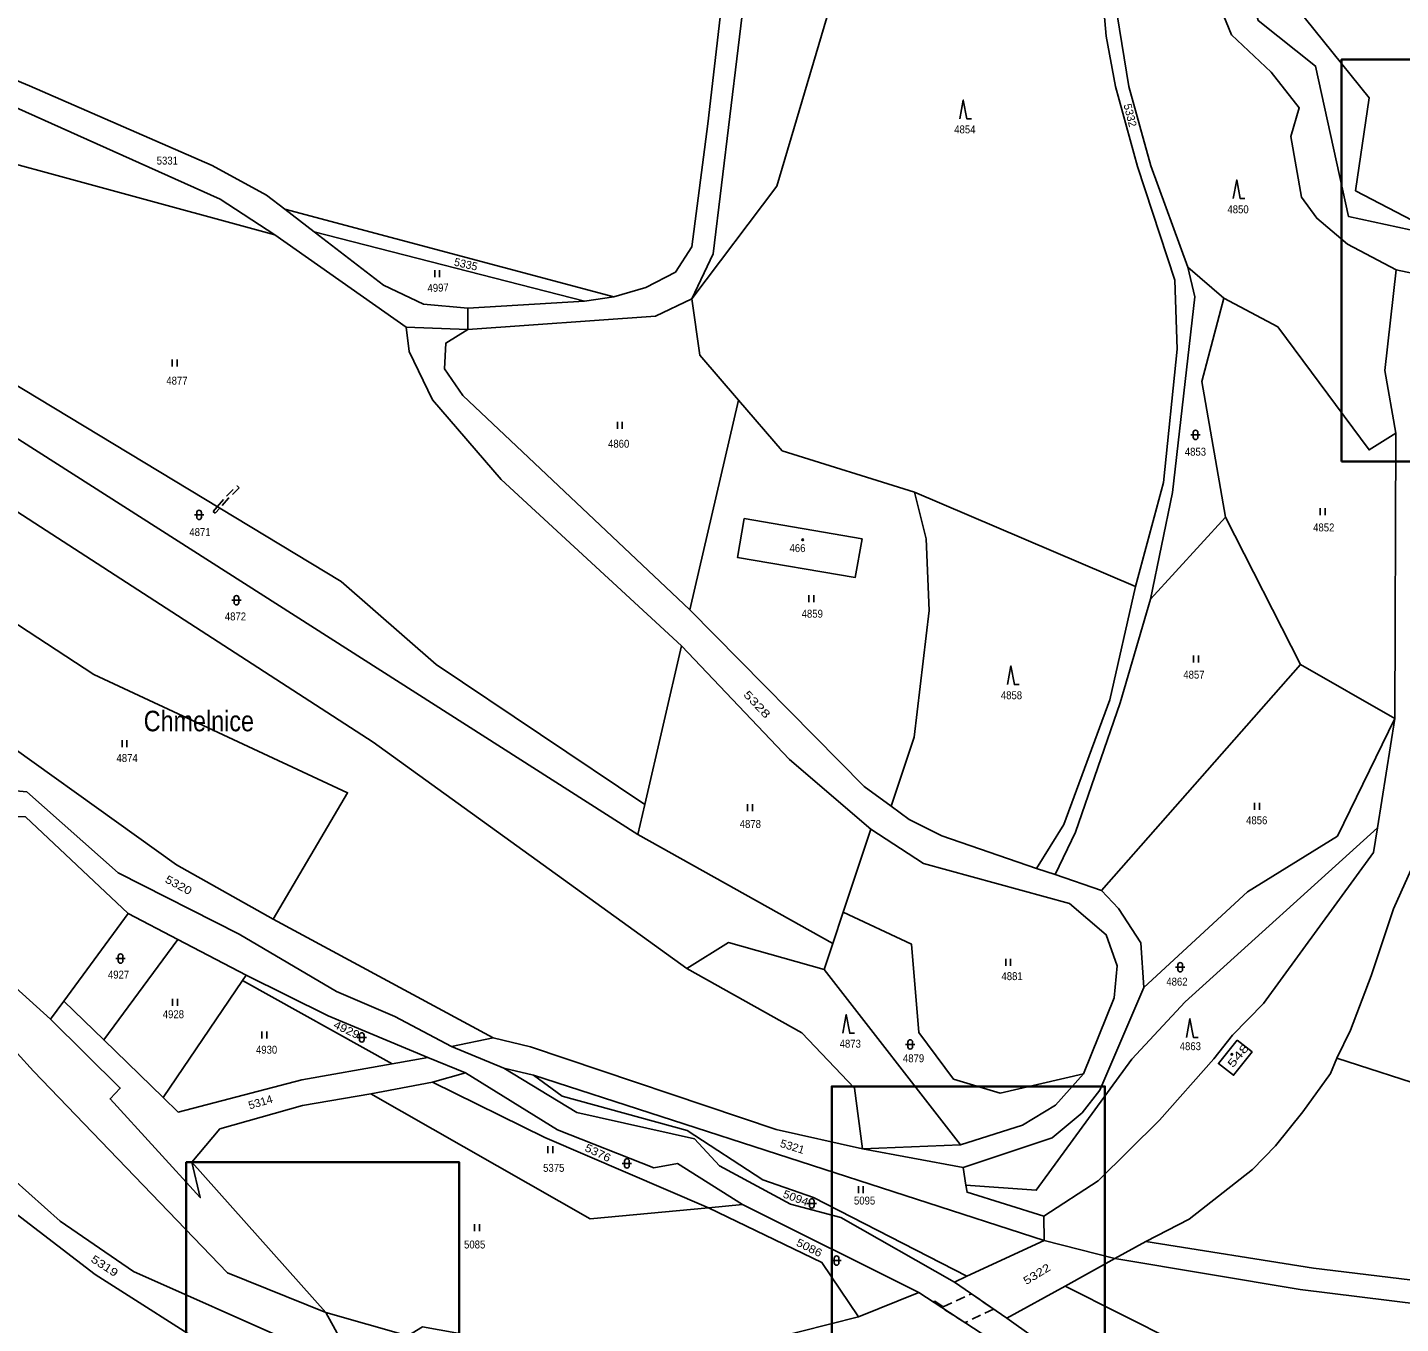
# Model space of a CAD drawing. Extents: x -665688 to -664583, y -1006118 to -1004927.
# Drawn here: x -665191.6 to -664897.5, y -1005454.1 to -1005176.4 of the extents above; entities that cross this region are included whole.
import ezdxf
from ezdxf.enums import TextEntityAlignment as Align

# ---------------------------------------------------------------- set-up
doc = ezdxf.new("R2010")
doc.units = 0
doc.header["$LTSCALE"] = 0.68
doc.linetypes.add('MEDIUM_DASHED', pattern=[4.5, 3, -1.5])
for name, color, linetype, lineweight in [('1', 7, 'Continuous', 25), ('25', 7, 'Continuous', 25), ('27', 7, 'MEDIUM_DASHED', 25), ('55', 7, 'Continuous', 35)]:
    doc.layers.add(name, color=color, linetype=linetype, lineweight=lineweight)
for name, color, linetype in [('15', 7, 'Continuous'), ('18', 7, 'Continuous'), ('19', 7, 'Continuous')]:
    doc.layers.add(name, color=color, linetype=linetype)

msp = doc.modelspace()

# ---------------------------------------------------------------- linework, layer by layer
at = {"layer": '1'}
for p, q in [((-665097.3, -1005241.05), (-665097.26, -1005236.54)), ((-665072.31, -1005234.98), (-665097.26, -1005236.54)), ((-665097.3, -1005241.05), (-665110.5, -1005240.56)), ((-664898.65, -1005324.46), (-664898.46, -1005263.33)), ((-664918.88, -1005312.89), (-664898.65, -1005324.46)), ((-664898.65, -1005324.46), (-664902.37, -1005347.86)), ((-664971.46, -1005357.88), (-664975.48, -1005356.59)), ((-665170.08, -1005366.25), (-665159.4, -1005371.83)), ((-665159.4, -1005371.83), (-665144.78, -1005379.46)), ((-665019.11, -1005372.67), (-665020.96, -1005378.24)), ((-665091.86, -1005392.84), (-665100.81, -1005394.75)), ((-665089.55, -1005399.37), (-665100.81, -1005394.75)), ((-665105.89, -1005397.05), (-665097.79, -1005400.37)), ((-665089.55, -1005399.37), (-665083.2, -1005400.84)), ((-665118.08, -1005404.88), (-665104.85, -1005402.34)), ((-664991.18, -1005420.63), (-665012.73, -1005416.63)), ((-665038.41, -1005428.56), (-665000.67, -1005447.45)), ((-664969.3, -1005446.1), (-664958.68, -1005440.16)), ((-664981.8, -1005452.97), (-664993.04, -1005445.2)), ((-664981.8, -1005452.97), (-664969.3, -1005446.1)), ((-665000.67, -1005447.45), (-665013.61, -1005452.67)), ((-665000.67, -1005447.45), (-664985.67, -1005457.24))]:
    msp.add_line(p, q, dxfattribs=at)
for points in [[(-664895.39, -1005219.73), (-664908.63, -1005216.84), (-664915.67, -1005184.63), (-664927.97, -1005174.84), (-664931.29, -1005161.96), (-664923.13, -1005157.75), (-664909.4, -1005145.58), (-664903.94, -1005133.92), (-664903.15, -1005127.85), (-664912.19, -1005084.06), (-664891.68, -1005067.49), (-664871.95, -1005045.77), (-664858.98, -1005033.99), (-664851.57, -1005033.48)], [(-664894.9, -1005217.74), (-664907.14, -1005211.36), (-664904.2, -1005191.46), (-664923.77, -1005167.11), (-664902.42, -1005142.29), (-664899.45, -1005128.56), (-664907.27, -1005091.69), (-664905.43, -1005083.63), (-664892.51, -1005077.23), (-664870.34, -1005046.85), (-664858.99, -1005037.17), (-664850.64, -1005036.62)], [(-665136.5, -1005215.33), (-665140.44, -1005212.3), (-665152.07, -1005205.93), (-665191.17, -1005188.9), (-665218.73, -1005177.39), (-665216.13, -1005170.52), (-665206.49, -1005145), (-665182.51, -1005081.53)], [(-665049.31, -1005234.5), (-665044.7, -1005224.87), (-665033.98, -1005136.54), (-665026.72, -1005106.52)], [(-665001.26, -1005109.58), (-665031.11, -1005210.37), (-665049.31, -1005234.5)], [(-664968.96, -1005115.26), (-664961.42, -1005140.2), (-664960.58, -1005145.04), (-664961.76, -1005164.25), (-664960.54, -1005178.21), (-664958.55, -1005188.98), (-664953.84, -1005206.17), (-664945.82, -1005230.5), (-664945.31, -1005245.28), (-664948.24, -1005273.87), (-664954.26, -1005296.16), (-665001.62, -1005275.92)], [(-665035.77, -1005123.25), (-665038.71, -1005135.19), (-665045.89, -1005196.99), (-665049.31, -1005223.37), (-665052.82, -1005228.77), (-665059.13, -1005232.1), (-665065.99, -1005234.1)], [(-664943, -1005227.75), (-664950.93, -1005206.04), (-664955.68, -1005188.99), (-664958.69, -1005170.55), (-664939.22, -1005164.33)], [(-664939.22, -1005164.33), (-664933.7, -1005177.92), (-664925.15, -1005185.97), (-664919.15, -1005193.6), (-664920.98, -1005199.71), (-664918.67, -1005212.71), (-664915.42, -1005217.25), (-664908.82, -1005222.82), (-664898.36, -1005228.3)], [(-665240.86, -1005177.51), (-665205.31, -1005188.54), (-665150.34, -1005213.14), (-665138.6, -1005220.79)], [(-665059.37, -1005342.9), (-665104.09, -1005312.9), (-665124.43, -1005295.1), (-665225.03, -1005234.3), (-665246.42, -1005229.05), (-665242.48, -1005192.49)], [(-665242.48, -1005192.49), (-665138.6, -1005220.79), (-665110.5, -1005240.56)], [(-665399.75, -1005208.35), (-665376.11, -1005222.26), (-665358.6, -1005232.91), (-665344.4, -1005243.08), (-665327.83, -1005258.99), (-665299.41, -1005297.42), (-665287.03, -1005311.31), (-665268.55, -1005328.24), (-665251.87, -1005341.72), (-665211.4, -1005376.84), (-665190.33, -1005399.99), (-665148.79, -1005443.19), (-665127.68, -1005451.74), (-665121.7, -1005462.65), (-665134.58, -1005458.21)], [(-665050.35, -1005378.04), (-665117.56, -1005329.51), (-665248.06, -1005245.09), (-665261.76, -1005239.56), (-665293.79, -1005218.72), (-665304.45, -1005209.39)], [(-665097.26, -1005236.54), (-665106.75, -1005235.64), (-665115.37, -1005231.58), (-665130.24, -1005220.14)], [(-664951.06, -1005298.9), (-664946.29, -1005275.99), (-664941.51, -1005234.09), (-664943, -1005227.75)], [(-664898.46, -1005263.33), (-664904.2, -1005266.89), (-664923.76, -1005240.51), (-664935.35, -1005234.38), (-664943, -1005227.75)], [(-664898.36, -1005228.3), (-664900.84, -1005249.89), (-664898.46, -1005263.33)], [(-664898.36, -1005228.3), (-664873.52, -1005233.6), (-664874.22, -1005299.23)], [(-665097.3, -1005241.05), (-665057.09, -1005238.2), (-665049.31, -1005234.5)], [(-665049.31, -1005234.5), (-665047.61, -1005246.59), (-665039.32, -1005256.22), (-665049.72, -1005301.17)], [(-664934.98, -1005281.28), (-664940.03, -1005252.24), (-664935.35, -1005234.38)], [(-665247.28, -1005237.07), (-665218.64, -1005248.65), (-665060.85, -1005349.31)], [(-665110.5, -1005240.56), (-665109.84, -1005245.77), (-665104.86, -1005256.16), (-665090.12, -1005273.19), (-665051.5, -1005308.87), (-665059.37, -1005342.9)], [(-665049.72, -1005301.17), (-665098.35, -1005255.21), (-665102.3, -1005249.51), (-665102, -1005243.98), (-665097.3, -1005241.05)], [(-665001.62, -1005275.92), (-665029.94, -1005267.11), (-665039.32, -1005256.22)], [(-665001.62, -1005275.92), (-664999.1, -1005285.91), (-664998.44, -1005301.31), (-665001.69, -1005328.42), (-665006.62, -1005343.23)], [(-665186.72, -1005388.88), (-665231.73, -1005348.14), (-665247.24, -1005335.03), (-665262.9, -1005322.2), (-665284.22, -1005302.33), (-665295.64, -1005288.54), (-665288.78, -1005281.42)], [(-665288.78, -1005281.42), (-665278.12, -1005293.76), (-665254.75, -1005298.72), (-665246.23, -1005320.3), (-665241.95, -1005328.41), (-665229.65, -1005333.27), (-665213.43, -1005330.83), (-665203.9, -1005345.02), (-665192.06, -1005345.49), (-665170.08, -1005366.25)], [(-664934.98, -1005281.28), (-664918.88, -1005312.89), (-664961.49, -1005361.3), (-664971.46, -1005357.88)], [(-664971.46, -1005357.88), (-664967.09, -1005348.78), (-664957.49, -1005321.11), (-664951.06, -1005298.9), (-664934.98, -1005281.28)], [(-664975.48, -1005356.59), (-664969.6, -1005347.14), (-664959.71, -1005320.47), (-664954.26, -1005296.16)], [(-665139.02, -1005367.43), (-665159.72, -1005355.83), (-665207.38, -1005321.62), (-665218.42, -1005320.08), (-665199.64, -1005300.53)], [(-665199.64, -1005300.53), (-665177.42, -1005315.04), (-665123.06, -1005340.35), (-665139.02, -1005367.43)], [(-665006.62, -1005343.23), (-665012.38, -1005338.99), (-665049.72, -1005301.17)], [(-665051.5, -1005308.87), (-665028.39, -1005333.21), (-665010.97, -1005348.18), (-665016.87, -1005365.92), (-665019.11, -1005372.67), (-665060.85, -1005349.31), (-665059.37, -1005342.9)], [(-664911.11, -1005397.23), (-664908.16, -1005391.22), (-664903.76, -1005379.6), (-664898.99, -1005365.23), (-664880.44, -1005324.02), (-664875.64, -1005308.45)], [(-665100.81, -1005394.75), (-665112.89, -1005388.29), (-665125.42, -1005382.92), (-665146.27, -1005370.65), (-665172.18, -1005357.52), (-665191.77, -1005340.12), (-665198.15, -1005339.57), (-665203.62, -1005332.13), (-665212.87, -1005325.35), (-665222.91, -1005324.76)], [(-664898.65, -1005324.46), (-664910.98, -1005349.63), (-664930.26, -1005361.6), (-664952.48, -1005382.07)], [(-664975.48, -1005356.59), (-664995.7, -1005349.58), (-665002.76, -1005346.07), (-665006.62, -1005343.23)], [(-665010.97, -1005348.18), (-664999.64, -1005355.54), (-664968.37, -1005364.11), (-664960.56, -1005370.78), (-664958.18, -1005377.42), (-664958.78, -1005384.32), (-664965.36, -1005400.61)], [(-664902.37, -1005347.86), (-664943.61, -1005385.12), (-664955.01, -1005397.41), (-664975.49, -1005425.51), (-664990.58, -1005424.46), (-664991.18, -1005420.63)], [(-664902.37, -1005347.86), (-664903.22, -1005353.17), (-664926.83, -1005385.53), (-664933.44, -1005392.32), (-664937.47, -1005397.34), (-664949.13, -1005410.53), (-664962.23, -1005423.51), (-664973.85, -1005431.1)], [(-664952.48, -1005382.07), (-664953.08, -1005372.54), (-664957.87, -1005365.15), (-664961.49, -1005361.3)], [(-665170.08, -1005366.25), (-665183.86, -1005384.99), (-665186.72, -1005388.88)], [(-665016.87, -1005365.92), (-665002.22, -1005372.83), (-665000.64, -1005391.69), (-664993.21, -1005401.74), (-664983.24, -1005404.71), (-664965.36, -1005400.61)], [(-665012.73, -1005416.63), (-665031.21, -1005412.54), (-665083.85, -1005394.79), (-665091.86, -1005392.84), (-665139.02, -1005367.43)], [(-665159.4, -1005371.83), (-665175.28, -1005393.3), (-665183.86, -1005384.99)], [(-665020.96, -1005378.24), (-665041.41, -1005372.47), (-665050.35, -1005378.04)], [(-664847.73, -1005373.11), (-664853.38, -1005372.05), (-664890.31, -1005403.96), (-664911.11, -1005397.23)], [(-665050.35, -1005378.04), (-665025.75, -1005391.78), (-665014.41, -1005403.65), (-665012.73, -1005416.63)], [(-665020.96, -1005378.24), (-664991.72, -1005415.78), (-665012.73, -1005416.63)], [(-665145.53, -1005380.57), (-665162.55, -1005405.66), (-665175.28, -1005393.3)], [(-665105.89, -1005397.05), (-665113.52, -1005398.42), (-665145.53, -1005380.57), (-665144.78, -1005379.46)], [(-665144.78, -1005379.46), (-665127.19, -1005388.15), (-665105.89, -1005397.05)], [(-664991.18, -1005420.63), (-664972.09, -1005414.33), (-664965.7, -1005408.91), (-664961.91, -1005404.06), (-664952.48, -1005382.07)], [(-665156.4, -1005419.5), (-665154.61, -1005427.1), (-665173.94, -1005405.95), (-665171.75, -1005403.64), (-665186.72, -1005388.88)], [(-665113.52, -1005398.42), (-665132.82, -1005401.87), (-665159.35, -1005408.77), (-665162.55, -1005405.66)], [(-664993.04, -1005445.2), (-665017.35, -1005431.35), (-665028.16, -1005428.51), (-665043.37, -1005420.31), (-665048.74, -1005414.54), (-665073.92, -1005408.87), (-665089.55, -1005399.37)], [(-664911.11, -1005397.23), (-664912.46, -1005400.49), (-664918.41, -1005408.69), (-664924.27, -1005416.02), (-664929.2, -1005421.1), (-664942.75, -1005431.69), (-664952, -1005436.49), (-664958.68, -1005440.16), (-664973.84, -1005436.33), (-664973.85, -1005431.1)], [(-665045.75, -1005429.26), (-665080.8, -1005414.25), (-665104.85, -1005402.34), (-665097.79, -1005400.37)], [(-665097.79, -1005400.37), (-665078.05, -1005412.57), (-665057.45, -1005420.7), (-665052.37, -1005419.81), (-665038.41, -1005428.56)], [(-665083.2, -1005400.84), (-664973.84, -1005436.33), (-664990.35, -1005443.96)], [(-665083.2, -1005400.84), (-665077.11, -1005405.36), (-665050.32, -1005412.75), (-665034.07, -1005423.33), (-665023.2, -1005427.08), (-664990.35, -1005443.96), (-664993.04, -1005445.2)], [(-664965.36, -1005400.61), (-664971.4, -1005407.3), (-664978.47, -1005411.61), (-664991.72, -1005415.78)], [(-665156.4, -1005419.5), (-665150.41, -1005412.37), (-665132.72, -1005407.37), (-665118.08, -1005404.88)], [(-665118.08, -1005404.88), (-665071.08, -1005431.67), (-665045.75, -1005429.26)], [(-665136.29, -1005477.24), (-665150.22, -1005460.69), (-665177.15, -1005443.61), (-665221.19, -1005409.78), (-665210.58, -1005407.96)], [(-665210.58, -1005407.96), (-665198.15, -1005420.12), (-665184.6, -1005432.15), (-665168.91, -1005442.94), (-665134.58, -1005458.21), (-665131.02, -1005461.53)], [(-665013.61, -1005452.67), (-665032.2, -1005457.35), (-665049.69, -1005459.74), (-665076.88, -1005460.21), (-665107.01, -1005454.78), (-665110.17, -1005456.74), (-665127.68, -1005451.74), (-665156.4, -1005419.5)], [(-664973.85, -1005431.1), (-664990.34, -1005425.94), (-664990.58, -1005424.46)], [(-665013.61, -1005452.67), (-665021.41, -1005441.03), (-665045.75, -1005429.26), (-665038.41, -1005428.56)], [(-664812.89, -1005451.45), (-664818.34, -1005452.22), (-664821.75, -1005452.39), (-664832, -1005452.23), (-664844.79, -1005450.86), (-664916.08, -1005442.22), (-664952, -1005436.49)], [(-664958.68, -1005440.16), (-664918.99, -1005446.77), (-664835.18, -1005457.14), (-664824.19, -1005457.34), (-664809.08, -1005455.92), (-664802.4, -1005456.42), (-664792.15, -1005466.99), (-664796.78, -1005468.06), (-664803.23, -1005465.97)], [(-664969.3, -1005446.1), (-664945.43, -1005458.11), (-664870.22, -1005475.95), (-664843.38, -1005478.52), (-664808.84, -1005489.57), (-664807.3, -1005497.72)], [(-664807.3, -1005497.72), (-664823.52, -1005498.49), (-664831.43, -1005490.72), (-664845.63, -1005484.35), (-664861.39, -1005491.91), (-664864, -1005488.5), (-664869.71, -1005485.89), (-664886.34, -1005486.35), (-664888.54, -1005481.42), (-664895.39, -1005478.51), (-664911.15, -1005478.85), (-664917.14, -1005475.22), (-664920.29, -1005468.16), (-664939.44, -1005469.7), (-664948.5, -1005477.86), (-664952.19, -1005476.3), (-664954.45, -1005466.18), (-664962.99, -1005461.77), (-664976.12, -1005457.02), (-664981.8, -1005452.97)]]:
    msp.add_lwpolyline(points, dxfattribs=at)
for points in [[(-665136.5, -1005215.33), (-665065.99, -1005234.1), (-665072.31, -1005234.98), (-665130.24, -1005220.14)], [(-665038.07, -1005281.58), (-665039.49, -1005289.96), (-665014.27, -1005294.21), (-665012.82, -1005285.97)], [(-664932.47, -1005393.36), (-664936.49, -1005398.39), (-664933.24, -1005400.88), (-664929.25, -1005395.88)]]:
    msp.add_lwpolyline(points, close=True, dxfattribs=at)
at = {"layer": '25'}
for p, q in [((-665104.357, -1005229.855), (-665104.357, -1005228.355)), ((-665103.323, -1005229.855), (-665103.323, -1005228.355)), ((-665160.627, -1005249.025), (-665160.627, -1005247.525)), ((-665159.593, -1005249.025), (-665159.593, -1005247.525)), ((-665065.237, -1005262.335), (-665065.237, -1005260.835)), ((-665064.203, -1005262.335), (-665064.203, -1005260.835)), ((-664942.37, -1005263.66), (-664940.37, -1005263.66)), ((-664941.87, -1005264.16), (-664941.87, -1005263.16)), ((-664940.87, -1005263.16), (-664940.87, -1005264.16)), ((-665155.87, -1005280.82), (-665153.87, -1005280.82)), ((-665155.37, -1005281.32), (-665155.37, -1005280.32)), ((-665154.37, -1005280.32), (-665154.37, -1005281.32)), ((-664914.667, -1005280.895), (-664914.667, -1005279.395)), ((-664913.633, -1005280.895), (-664913.633, -1005279.395)), ((-665147.86, -1005299.1), (-665145.86, -1005299.1)), ((-665147.36, -1005299.6), (-665147.36, -1005298.6)), ((-665146.36, -1005298.6), (-665146.36, -1005299.6)), ((-665024.207, -1005299.535), (-665024.207, -1005298.035)), ((-665023.173, -1005299.535), (-665023.173, -1005298.035)), ((-664941.797, -1005312.425), (-664941.797, -1005310.925)), ((-664940.763, -1005312.425), (-664940.763, -1005310.925)), ((-665171.367, -1005330.615), (-665171.367, -1005329.115)), ((-665170.333, -1005330.615), (-665170.333, -1005329.115)), ((-665037.357, -1005344.265), (-665037.357, -1005342.765)), ((-665036.323, -1005344.265), (-665036.323, -1005342.765)), ((-664928.727, -1005344.015), (-664928.727, -1005342.515)), ((-664927.693, -1005344.015), (-664927.693, -1005342.515)), ((-665172.69, -1005375.88), (-665170.69, -1005375.88)), ((-665172.19, -1005376.38), (-665172.19, -1005375.38)), ((-665171.19, -1005375.38), (-665171.19, -1005376.38)), ((-664982.047, -1005377.465), (-664982.047, -1005375.965)), ((-664981.013, -1005377.465), (-664981.013, -1005375.965)), ((-664945.64, -1005377.74), (-664943.64, -1005377.74)), ((-664945.14, -1005378.24), (-664945.14, -1005377.24)), ((-664944.14, -1005377.24), (-664944.14, -1005378.24)), ((-665160.547, -1005386.045), (-665160.547, -1005384.545)), ((-665159.513, -1005386.045), (-665159.513, -1005384.545)), ((-665141.387, -1005393.005), (-665141.387, -1005391.505)), ((-665140.353, -1005393.005), (-665140.353, -1005391.505)), ((-665121.01, -1005392.77), (-665119.01, -1005392.77)), ((-665120.51, -1005393.27), (-665120.51, -1005392.27)), ((-665119.51, -1005392.27), (-665119.51, -1005393.27)), ((-665003.51, -1005394.29), (-665001.51, -1005394.29)), ((-665003.01, -1005394.79), (-665003.01, -1005393.79)), ((-665002.01, -1005393.79), (-665002.01, -1005394.79)), ((-665080.117, -1005417.555), (-665080.117, -1005416.055)), ((-665079.083, -1005417.555), (-665079.083, -1005416.055)), ((-665064.2, -1005419.79), (-665062.2, -1005419.79)), ((-665063.7, -1005420.29), (-665063.7, -1005419.29)), ((-665062.7, -1005419.29), (-665062.7, -1005420.29)), ((-665013.617, -1005426.155), (-665013.617, -1005424.655)), ((-665012.583, -1005426.155), (-665012.583, -1005424.655)), ((-665024.59, -1005428.36), (-665022.59, -1005428.36)), ((-665024.09, -1005428.86), (-665024.09, -1005427.86)), ((-665023.09, -1005427.86), (-665023.09, -1005428.86)), ((-665095.847, -1005434.315), (-665095.847, -1005432.815)), ((-665094.813, -1005434.315), (-665094.813, -1005432.815)), ((-665019.29, -1005440.6), (-665017.29, -1005440.6)), ((-665018.79, -1005441.1), (-665018.79, -1005440.1)), ((-665017.79, -1005440.1), (-665017.79, -1005441.1))]:
    msp.add_line(p, q, dxfattribs=at)
for points in [[(-664991.91, -1005195.94), (-664991.16, -1005191.94), (-664990.41, -1005195.94), (-664989.41, -1005195.94)], [(-664933.3, -1005213.02), (-664932.55, -1005209.02), (-664931.8, -1005213.02), (-664930.8, -1005213.02)], [(-664981.68, -1005317.16), (-664980.93, -1005313.16), (-664980.18, -1005317.16), (-664979.18, -1005317.16)], [(-665016.95, -1005391.9), (-665016.2, -1005387.9), (-665015.45, -1005391.9), (-665014.45, -1005391.9)], [(-664943.32, -1005392.79), (-664942.57, -1005388.79), (-664941.82, -1005392.79), (-664940.82, -1005392.79)]]:
    msp.add_lwpolyline(points, dxfattribs=at)
for centre in [(-665025.56, -1005286.14), (-664933.6, -1005396.42)]:
    msp.add_circle(centre, 0.175, dxfattribs=at)
for centre, start, end in [((-664941.37, -1005263.16), 0.101, 180.00143), ((-664941.37, -1005264.16), 180.10243, 0.00286), ((-665154.87, -1005280.32), 0.101, 180.00143), ((-665154.87, -1005281.32), 180.10243, 0.00286), ((-665146.86, -1005298.6), 0.101, 180.00143), ((-665146.86, -1005299.6), 180.10243, 0.00286), ((-665171.69, -1005375.38), 0.101, 180.00143), ((-665171.69, -1005376.38), 180.10243, 0.00286), ((-664944.64, -1005377.24), 0.101, 180.00143), ((-664944.64, -1005378.24), 180.10243, 0.00286), ((-665120.01, -1005392.27), 0.101, 180.00143), ((-665120.01, -1005393.27), 180.10243, 0.00286), ((-665002.51, -1005393.79), 0.101, 180.00143), ((-665002.51, -1005394.79), 180.10243, 0.00286), ((-665063.2, -1005419.29), 0.101, 180.00143), ((-665063.2, -1005420.29), 180.10243, 0.00286), ((-665023.59, -1005427.86), 0.101, 180.00143), ((-665023.59, -1005428.86), 180.10243, 0.00286), ((-665018.29, -1005440.1), 0.101, 180.00143), ((-665018.29, -1005441.1), 180.10243, 0.00286)]:
    msp.add_arc(centre, 0.5, start, end, dxfattribs=at)
at = {"layer": '27'}
for points in [[(-665146.69, -1005274.57), (-665146.27, -1005274.99), (-665148.55, -1005277.25), (-665150.44, -1005279.38), (-665151.4, -1005280.47), (-665151.85, -1005280.08), (-665150.96, -1005279.07), (-665148.99, -1005276.83)], [(-664997.63, -1005449.44), (-664997.23, -1005449.28), (-664995.44, -1005450.48), (-664989.37, -1005447.74), (-664984.65, -1005451), (-664990.78, -1005453.9)]]:
    msp.add_lwpolyline(points, close=True, dxfattribs=at)
at = {"layer": '55'}
for points in [[(-664910.13, -1005269.36), (-664910.13, -1005183.26), (-664851.63, -1005183.26), (-664851.63, -1005269.36)], [(-665019.3, -1005489.36), (-665019.3, -1005403.26), (-664960.8, -1005403.26), (-664960.8, -1005489.36)], [(-665157.63, -1005505.61), (-665157.63, -1005419.51), (-665099.13, -1005419.51), (-665099.13, -1005505.61)]]:
    msp.add_lwpolyline(points, close=True, dxfattribs=at)

# ---------------------------------------------------------------- texts
at = {"layer": '15', "width": 0.85}
msp.add_text('Chmelnice', height=4.4, dxfattribs=at).set_placement((-665154.91, -1005327.18), align=Align.CENTER)
at = {"layer": '18'}
for s, rotation, p in [('5332', 284.302, (-664956.194, -1005195.3945)), ('5335', 347.203, (-665097.8878, -1005227.9241))]:
    msp.add_text(s, height=1.7, rotation=rotation, dxfattribs=at).set_placement(p, align=Align.CENTER)
at = {"layer": '18', "width": 0.9}
for s, p in [('4854', (-664990.7995, -1005199.06)), ('5331', (-665161.6695, -1005205.74)), ('4850', (-664932.2695, -1005216.18)), ('4877', (-665159.5995, -1005252.89)), ('4860', (-665064.9695, -1005266.41)), ('4853', (-664941.3995, -1005268.12)), ('4871', (-665154.6695, -1005285.34)), ('4852', (-664913.9095, -1005284.35)), ('4872', (-665147.0695, -1005303.42)), ('4859', (-665023.4895, -1005302.84)), ('4857', (-664941.7195, -1005315.89)), ('4858', (-664980.8095, -1005320.31)), ('4874', (-665170.2795, -1005333.76)), ('4878', (-665036.7595, -1005347.89)), ('4856', (-664928.2695, -1005347.1)), ('4927', (-665172.1195, -1005380.17)), ('4881', (-664980.6795, -1005380.5)), ('4862', (-664945.3595, -1005381.68)), ('4928', (-665160.3695, -1005388.66)), ('4873', (-665015.3495, -1005394.97)), ('4930', (-665140.3995, -1005396.26)), ('4879', (-665001.7895, -1005398.1)), ('4863', (-664942.4895, -1005395.51)), ('5375', (-665078.8795, -1005421.58)), ('5095', (-665012.2795, -1005428.59)), ('5085', (-665095.8195, -1005438))]:
    msp.add_text(s, height=1.7, dxfattribs=at).set_placement(p, align=Align.CENTER)
at = {"layer": '18'}
for s, rotation, width, p in [('4997', 1.7, 0.9, (-665103.6317, -1005232.9815)), ('5328', 313.402, 1.4, (-665035.9492, -1005322.003)), ('5320', 331.703, 1.2, (-665159.6544, -1005360.8756)), ('4929', 334.703, 1.15, (-665123.6157, -1005391.8805)), ('5314', 16.6, 1.05, (-665141.4698, -1005407.466)), ('5376', 334.303, 1.15, (-665069.7831, -1005418.2691)), ('5321', 342.803, 1.05, (-665027.9908, -1005416.9805)), ('5094', 339.603, 1.1, (-665027.3242, -1005427.9694)), ('5086', 333.403, 1.15, (-665024.5066, -1005438.5971)), ('5319', 327.003, 1.25, (-665175.5624, -1005442.4438)), ('5322', 31.5, 1.25, (-664974.9351, -1005444.2067))]:
    msp.add_text(s, height=1.7, rotation=rotation, dxfattribs=dict(at, width=width)).set_placement(p, align=Align.CENTER)
at = {"layer": '19', "width": 0.9}
msp.add_text('466', height=1.7, dxfattribs=at).set_placement((-665028.36, -1005288.78))
at = {"layer": '19', "width": 1.5}
msp.add_text('548', height=1.7, rotation=50.2, dxfattribs=at).set_placement((-664933.415, -1005399.419))

doc.saveas('drawing.dxf')
